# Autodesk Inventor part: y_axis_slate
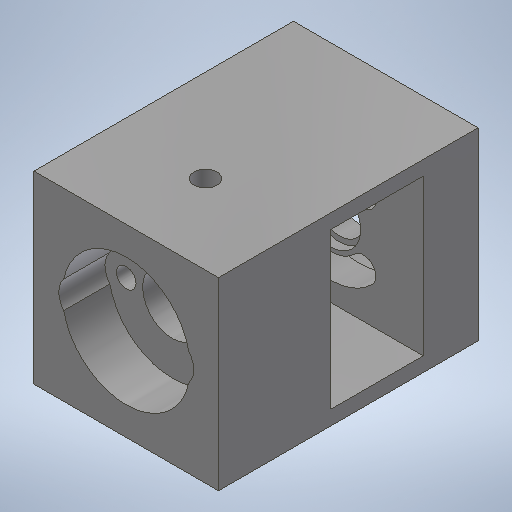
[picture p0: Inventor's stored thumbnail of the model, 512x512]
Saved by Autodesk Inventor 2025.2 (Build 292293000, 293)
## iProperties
Created: 2025-04
Part Number: y_axis_slate
Material: 1.0037 S235JR
Document SubType Name: Modeling
Designer: BennF
Density: 7.85 g/cm^3
Appearance: Stahl
Author: BennF
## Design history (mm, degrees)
sketch "Sketch2"
  geometry: L1 (16, 16)-(-16, 16); L2 (-16, 16)-(-16, -16); L3 (-16, -16)-(16, -16); L4 (16, -16)-(16, 16); 3 further points
  constraints: 8 end point, 2 midpoint, 2 parallel, 1 horizontal, 1 horizontal alignment, 1 perpendicular, 1 vertical alignment
  dimensions: "d0" = 32 distance of L1.start L1.end; "d1" = 32 distance of L3.end L1.start
extrude "Extrusion1" new body sketch "Sketch2" distance "d2" = 45; taper "d3" = 0 deg
workplane "Work Plane1"
sketch "Sketch3"
  geometry: L1 (4.9, 0)-(4.9, 8); L2 (4.9, 8)-(10.85, 8); L3 (10.85, 8)-(10.85, 19.5); L4 (16, 0)-(16, 45); L5 (0, 45)-(32, 45) reference; L6 (10.85, 19.5)-(2.5, 19.5); L7 (2.5, 19.5)-(2.5, 35.5); L8 (2.5, 35.5)-(10.85, 35.5); L9 (11.75, 37)-(11.75, 40.5); L10 (11.75, 40.5)-(2.5, 40.5); L11 (2.5, 40.5)-(2.5, 45); L12 (0, 0)-(32, 0) reference; L13 (10.85, 35.5)-(10.85, 37); L14 (10.85, 37)-(11.75, 37)
  constraints: 24 end point, 8 perpendicular, 3 vertical, 2 collinear, 2 point on line, 1 horizontal, 1 midpoint
  dimensions: "d4" = 22.2 diameter of L1 L4; "d5" = 10.3 diameter of L3 L4; "d7" = 27 diameter of L7 L4; "d8" = 8 distance of L1.start L1.end; "d10" = 4.5 distance of L10.end L11.end; "d12" = 16 distance of L6.end L7.end; "d38" = 8.5 diameter of L9 L4; "d39" = 1.5 distance of L8.end L13.end; "d40" = 3.5 distance between parallel lines of L10 L14
revolve "Revolution1" sketch "Sketch3" stored, may be unused: angle "d13" = 90 deg
sketch "Sketch4"
  geometry: L1 (0, -13.5)-(16, -13.5); L2 (16, -16)-(16, 16) reference; L3 (0, 13.5)-(16, 13.5); A1 r 13.5 centre (0, 0) between (0, -13.5) and (0, 13.5) reference; A2 r 13.5 centre (0, 0) between (0, 13.5) and (0, -13.5); 1 further point
  constraints: 4 end point, 4 point on circle, 2 horizontal, 2 point on line, 2 vertical alignment, 1 centre point, 1 coincident
extrude "Extrusion2" cut sketch "Sketch4" stored distance "d14" = 40; taper "d15" = 0 deg
sketch "Sketch5"
  geometry: L1 (5.657, -5.657)-(-5.657, 5.657); L2 (5.657, 5.657)-(-5.657, -5.657); C1 r 4.25 at (0, 0) reference; A1 r 8 centre (0, 0) between (5.657, -5.657) and (5.657, 5.657); A2 r 8 centre (0, 0) between (-5.657, -5.657) and (5.657, -5.657); A3 r 10.15 centre (0, 0) between (-7.177, -7.177) and (7.177, -7.177); A4 r 5.85 centre (0, 0) between (-4.137, -4.137) and (4.137, -4.137); A5 r 2.15 centre (-5.657, -5.657) between (-4.137, -4.137) and (-7.177, -7.177); A6 r 2.15 centre (5.657, -5.657) between (7.177, -7.177) and (4.137, -4.137); A7 r 8 centre (0, 0) between (5.657, 5.657) and (-5.657, 5.657); A8 r 10.15 centre (0, 0) between (7.177, 7.177) and (-7.177, 7.177); A9 r 5.85 centre (0, 0) between (4.137, 4.137) and (-4.137, 4.137); A10 r 2.15 centre (5.657, 5.657) between (4.137, 4.137) and (7.177, 7.177); A11 r 2.15 centre (-5.657, 5.657) between (-7.177, 7.177) and (-4.137, 4.137); 2 further points
  constraints: 22 point on circle, 11 centre point, 8 tangent, 4 end point, 3 coincident, 3 equal radius, 2 midpoint, 1 perpendicular, 1 vertical alignment
  dimensions: "d16" = 16 diameter of A1; "d17" = 2.15 radius of A5
extrude "Extrusion3" cut sketch "Sketch5" stored distance "d18" = 16 (= d16); taper "d19" = 0 deg
sketch "Sketch6"
  geometry: A1 r 8 centre (0, 0) between (-8, 0) and (8, 0); 1 further point
  constraints: 2 horizontal alignment, 2 point on circle, 1 centre point, 1 coincident
  dimensions: "d27" = 16 diameter of A1 (= d16)
hole "Hole1" sketch "Sketch6" at (-8, 0), (8, 0) diameter "d20" = 3.4; stored, may be unused: countersink angle "d24" = 90 deg, drill point angle "d26" = 0 deg; dims "d21" = 8, "d22" = 7.5, "d23" = 2, "d25" = 8
sketch "Sketch7"
  geometry: C1 r 3.7 at (-8, 0); C2 r 3.7 at (8, 0); 7 further points
  constraints: 2 centre point, 2 coincident, 1 equal radius, 2 other
  dimensions: "d28" = 7.4 diameter of C1
extrude "Extrusion4" cut sketch "Sketch7" stored distance "d29" = 10; taper "d30" = 0 deg
sketch "Sketch8"
  geometry: L1 (32, 19.5)-(32, 19.5); L2 (10.85, 19.5)-(21.15, 19.5) reference; L3 (10.85, 8)-(21.15, 8) reference; L4 (16, 8)-(16, 19.5); 5 further points
  constraints: 3 coincident, 3 midpoint, 2 end point, 1 perpendicular
hole "Hole2" sketch "Sketch8" at (16, 13.75) diameter "d31" = 3.2; stored, may be unused: countersink angle "d35" = 90 deg, drill point angle "d37" = 0 deg; dims "d32" = 6, "d33" = 4, "d34" = 6.7, "d36" = 8
body "Solid1"
